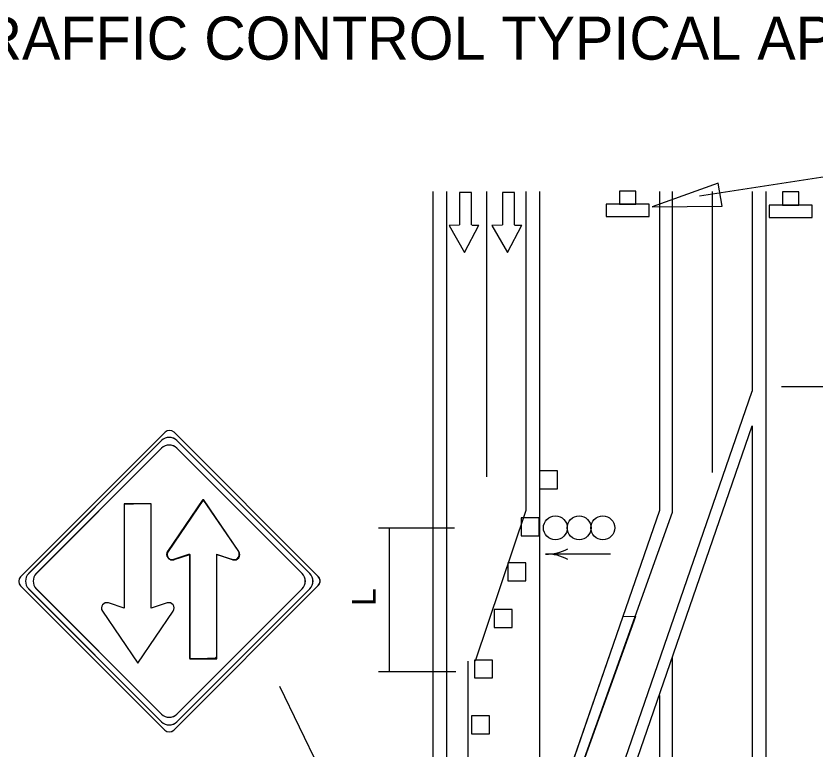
# Model space of a CAD drawing. Extents: x 1531.42 to 1538.58, y 1529.59 to 1539.57.
# Drawn here: x 1533.644 to 1535.649, y 1537.736 to 1539.575 of the extents above; entities that cross this region are included whole.
import ezdxf

# ---------------------------------------------------------------- set-up
doc = ezdxf.new("R2010")
doc.units = 0
for name, color, linetype in [('DETL-DIMS', 7, 'Continuous'), ('DETL-LINE', 7, 'Continuous'), ('DETL-NOTE', 7, 'Continuous'), ('DETL-TITL', 7, 'Continuous'), ('USER-BORD', 7, 'Continuous')]:
    doc.layers.add(name, color=color, linetype=linetype)

# ---------------------------------------------------------------- blocks, each defined once
blk = doc.blocks.new('PANEL0')
at = {"layer": 'USER-BORD'}
for centre in [(0.00309, -0.00012), (0.00928, -0.00012), (0.01546, -0.00012)]:
    blk.add_circle(centre, 0.00312, dxfattribs=at)
blk = doc.blocks.new('ZZZ')
at = {"layer": 'USER-BORD'}
blk.add_line((0.0185, 0), (0, 0), dxfattribs=at)
for centre, start, end in [((0.00034, 0.01233), 268.3695, 298.8797), ((0.00034, -0.01235), 61.1203, 91.6305)]:
    blk.add_arc(centre, 0.01234, start, end, dxfattribs=at)
blk = doc.blocks.new('R-BRD3')
at = {"layer": 'USER-BORD'}
for p, q in [((1.415, 2.996), (-1.412, 2.996)), ((-1.5, 2.909), (-1.5, 0.087)), ((-1.3, 2.95), (1.3, 2.95)), ((1.225, 2.875), (-1.225, 2.875)), ((1.502, 0.087), (1.502, 2.909)), ((-1.45, 0.2), (-1.45, 2.8)), ((1.45, 2.8), (1.45, 0.2)), ((-1.375, 2.725), (-1.375, 0.275)), ((1.375, 0.275), (1.375, 2.725)), ((-1.225, 0.125), (1.225, 0.125)), ((-1.412, 0), (1.415, 0)), ((1.3, 0.05), (-1.3, 0.05))]:
    blk.add_line(p, q, dxfattribs=at)
for centre, radius, start, end in [((-1.412, 2.909), 0.0875, 90, 180), ((1.415, 2.909), 0.0875, 0, 90), ((-1.3, 2.8), 0.15, 90, 180), ((-1.225, 2.725), 0.15, 90, 180), ((1.225, 2.725), 0.15, 0, 90), ((1.3, 2.8), 0.15, 0, 90), ((-1.225, 0.275), 0.15, 180, 270), ((1.225, 0.275), 0.15, 270, 0), ((-1.3, 0.2), 0.15, 180, 270), ((1.3, 0.2), 0.15, 270, 0), ((-1.412, 0.087), 0.0875, 180, 270), ((1.415, 0.087), 0.0875, 270, 0)]:
    blk.add_arc(centre, radius, start, end, dxfattribs=at)
blk = doc.blocks.new('W-BRD1')
at = {"layer": 'USER-BORD', "rotation": 45}
blk.add_blockref('R-BRD3', (1.0448, 1.0213), dxfattribs=at)

msp = doc.modelspace()

# ---------------------------------------------------------------- linework, layer by layer
at = {"layer": 'DETL-DIMS'}
for p, q in [((1536.0584, 1539.2298), (1535.359, 1539.1223)), ((1535.5651, 1538.6449), (1535.8056, 1538.6449)), ((1534.7442, 1538.29), (1534.554, 1538.29)), ((1534.5804, 1538.29), (1534.5804, 1537.9297)), ((1534.7477, 1537.9297), (1534.554, 1537.9297)), ((1534.5548, 1537.3801), (1534.3064, 1537.8927))]:
    msp.add_line(p, q, dxfattribs=at)
msp.add_lwpolyline([(1535.4162, 1539.0977), (1535.4066, 1539.1549), (1535.241, 1539.0959)], close=True, dxfattribs=at)
at = {"layer": 'DETL-LINE'}
for p, q in [((1534.6905, 1539.1347), (1534.6905, 1536.2958)), ((1534.724, 1539.1347), (1534.724, 1536.2958)), ((1534.7574, 1539.132), (1534.7574, 1539.051)), ((1534.7874, 1539.132), (1534.7574, 1539.132)), ((1534.7874, 1539.051), (1534.7874, 1539.132)), ((1534.8244, 1539.1347), (1534.8244, 1538.4186)), ((1534.8948, 1539.132), (1534.8649, 1539.132)), ((1534.8649, 1539.132), (1534.8649, 1539.051)), ((1534.8948, 1539.051), (1534.8948, 1539.132)), ((1534.9239, 1539.1347), (1534.9239, 1538.334)), ((1534.9574, 1539.1347), (1534.9574, 1537.4638)), ((1535.2586, 1539.1347), (1535.2586, 1538.334)), ((1535.2912, 1539.1347), (1535.2912, 1538.3287)), ((1535.3916, 1539.1347), (1535.3916, 1538.4291)), ((1535.492, 1539.1347), (1535.492, 1538.6335)), ((1535.5255, 1539.1347), (1535.5255, 1537.0031)), ((1534.731, 1539.0501), (1534.7574, 1539.051)), ((1534.731, 1539.0492), (1534.7698, 1538.9814)), ((1534.7698, 1538.9814), (1534.8058, 1539.0501)), ((1534.7882, 1539.0501), (1534.8058, 1539.0501)), ((1534.8384, 1539.0501), (1534.8649, 1539.051)), ((1534.8384, 1539.0492), (1534.8772, 1538.9814)), ((1534.8772, 1538.9814), (1534.9133, 1539.0501)), ((1534.8948, 1539.0501), (1534.9133, 1539.0501)), ((1534.9239, 1536.9925), (1535.492, 1538.6335)), ((1534.9574, 1536.9996), (1535.492, 1538.5463)), ((1535.492, 1538.5463), (1535.492, 1537.0031)), ((1534.018, 1538.5303), (1533.6552, 1538.1675)), ((1534.4024, 1538.1683), (1534.0405, 1538.5303)), ((1533.6756, 1538.176), (1534.0092, 1538.5096)), ((1534.0092, 1538.5096), (1533.6756, 1538.176)), ((1534.0477, 1538.5096), (1534.3813, 1538.176)), ((1534.3813, 1538.176), (1534.0477, 1538.5096)), ((1533.6948, 1538.1761), (1534.0092, 1538.4903)), ((1534.0476, 1538.4903), (1534.362, 1538.176)), ((1534.1132, 1538.362), (1534.0243, 1538.2316)), ((1534.1143, 1538.3613), (1534.0255, 1538.2309)), ((1534.1132, 1538.362), (1534.2019, 1538.2316)), ((1534.2031, 1538.2309), (1534.1143, 1538.3613)), ((1533.9384, 1538.3504), (1533.9154, 1538.3504)), ((1533.9154, 1538.3504), (1533.9154, 1538.1573)), ((1533.9834, 1538.3506), (1533.9166, 1538.3506)), ((1533.9166, 1538.3506), (1533.9384, 1538.3504)), ((1533.9834, 1538.1573), (1533.9834, 1538.3506)), ((1534.9239, 1538.334), (1534.7962, 1537.9561)), ((1535.2586, 1538.334), (1534.8358, 1537.1106)), ((1535.2912, 1538.3287), (1534.8543, 1537.1106)), ((1534.0792, 1538.2243), (1534.0395, 1538.2114)), ((1534.0407, 1538.2107), (1534.0804, 1538.2236)), ((1534.0791, 1538.2241), (1534.0791, 1538.1561)), ((1534.0803, 1538.2234), (1534.0803, 1538.1553)), ((1534.1471, 1538.2243), (1534.1868, 1538.2114)), ((1534.1472, 1538.2241), (1534.1472, 1538.1561)), ((1534.1482, 1538.2236), (1534.1879, 1538.2107)), ((1534.1483, 1538.1553), (1534.1483, 1538.2234)), ((1533.9154, 1538.1573), (1533.9154, 1538.0893)), ((1533.9834, 1538.0893), (1533.9834, 1538.1573)), ((1534.0791, 1538.1561), (1534.0791, 1537.9628)), ((1534.1472, 1538.1561), (1534.1472, 1537.963)), ((1533.6552, 1538.1451), (1534.0172, 1537.7831)), ((1534.0092, 1537.8039), (1533.6756, 1538.1375)), ((1533.6756, 1538.1375), (1534.0092, 1537.8039)), ((1534.0092, 1537.8232), (1533.6948, 1538.1375)), ((1534.0396, 1537.7831), (1534.4024, 1538.1459)), ((1534.3813, 1538.1375), (1534.0477, 1537.8039)), ((1534.362, 1538.1375), (1534.0477, 1537.8232)), ((1534.0477, 1537.8039), (1534.3813, 1538.1375)), ((1534.0803, 1538.1553), (1534.0803, 1537.9621)), ((1534.1483, 1537.9623), (1534.1483, 1538.1553)), ((1533.9155, 1538.0891), (1533.8758, 1538.102)), ((1534.023, 1538.102), (1533.9834, 1538.0891)), ((1533.8606, 1538.0818), (1533.9494, 1537.9514)), ((1533.9494, 1537.9514), (1534.0382, 1538.0818)), ((1534.0791, 1537.9628), (1534.146, 1537.9628)), ((1534.0803, 1537.9621), (1534.1471, 1537.9621)), ((1534.1472, 1537.963), (1534.1241, 1537.963)), ((1534.1253, 1537.9623), (1534.1483, 1537.9623)), ((1534.1471, 1537.9621), (1534.1253, 1537.9623)), ((1534.1432, 1537.9628), (1534.1471, 1537.9669)), ((1534.7777, 1537.9561), (1534.7777, 1536.6279)), ((1535.2912, 1537.9667), (1535.2912, 1537.1335)), ((1533.9492, 1537.9517), (1533.9507, 1537.9532)), ((1535.2586, 1537.8698), (1535.2586, 1537.1335))]:
    msp.add_line(p, q, dxfattribs=at)
for points in [[(1535.1587, 1539.1025), (1535.2, 1539.1025), (1535.2, 1539.1353), (1535.1587, 1539.1353)], [(1535.5676, 1539.1003), (1535.6089, 1539.1003), (1535.6089, 1539.1331), (1535.5676, 1539.1331)], [(1535.1251, 1539.1025), (1535.1251, 1539.0716), (1535.2333, 1539.0716), (1535.2333, 1539.1025)], [(1535.534, 1539.1003), (1535.534, 1539.0695), (1535.6422, 1539.0695), (1535.6422, 1539.1003)], [(1534.958, 1538.3886), (1535.0028, 1538.3886), (1535.0028, 1538.4334), (1534.958, 1538.4334)], [(1534.9122, 1538.2706), (1534.957, 1538.2706), (1534.957, 1538.3154), (1534.9122, 1538.3154)], [(1534.8787, 1538.1579), (1534.9235, 1538.1579), (1534.9235, 1538.2027), (1534.8787, 1538.2027)], [(1534.8444, 1538.0407), (1534.8892, 1538.0407), (1534.8892, 1538.0855), (1534.8444, 1538.0855)], [(1535.1679, 1538.0689), (1535.1987, 1538.068), (1534.8552, 1537.1115), (1534.8437, 1537.1317)], [(1534.795, 1537.9139), (1534.8398, 1537.9139), (1534.8398, 1537.9587), (1534.795, 1537.9587)], [(1534.7871, 1537.7738), (1534.8319, 1537.7738), (1534.8319, 1537.8186), (1534.7871, 1537.8186)]]:
    msp.add_lwpolyline(points, close=True, dxfattribs=at)
for points in [[(1534.8244, 1538.9847), (1534.8244, 1538.8847)], [(1535.3916, 1538.9847), (1535.3916, 1538.8847)], [(1534.8244, 1538.5847), (1534.8244, 1538.4847)], [(1535.3916, 1538.5847), (1535.3916, 1538.4847)]]:
    msp.add_lwpolyline(points, dxfattribs=at)
for centre, radius, start, end in [((1534.0285, 1538.4903), 0.0272, 45, 135), ((1534.0285, 1538.4903), 0.0272, 45, 135), ((1534.0292, 1538.5191), 0.0159, 45, 135), ((1534.0284, 1538.4711), 0.0272, 45, 135), ((1534.0354, 1538.2241), 0.0134, 145.7397, 288), ((1534.0365, 1538.2234), 0.0134, 145.7397, 288), ((1534.1909, 1538.2241), 0.0134, 252, 34.2603), ((1534.1921, 1538.2234), 0.0134, 252, 34.2603), ((1533.6665, 1538.1563), 0.0159, 135, 225), ((1533.6949, 1538.1567), 0.0272, 135, 225), ((1533.6949, 1538.1567), 0.0272, 135, 225), ((1533.7141, 1538.1568), 0.0272, 135, 225), ((1534.3428, 1538.1567), 0.0272, 315, 45), ((1534.362, 1538.1567), 0.0272, 315, 45), ((1534.362, 1538.1567), 0.0272, 315, 45), ((1534.3912, 1538.1571), 0.0159, 315, 45), ((1533.8717, 1538.0893), 0.0134, 72, 214.2603), ((1534.0272, 1538.0893), 0.0134, 325.7397, 108), ((1534.0284, 1537.8424), 0.0272, 225, 315), ((1534.0285, 1537.8232), 0.0272, 225, 315), ((1534.0285, 1537.8232), 0.0272, 225, 315), ((1534.0284, 1537.7943), 0.0159, 225, 315)]:
    msp.add_arc(centre, radius, start, end, dxfattribs=at)

# ---------------------------------------------------------------- block references
for name, p, xscale, yscale in [('W-BRD1', (1534.0314, 1537.779), 0.1814448, 0.18144479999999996), ('PANEL0', (1534.9679, 1538.2917), 9.618403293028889, 9.618403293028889), ('ZZZ', (1534.9732, 1538.2248), 8.807999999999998, 8.807999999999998)]:
    msp.add_blockref(name, p, dxfattribs=dict(at, xscale=xscale, yscale=yscale))

# ---------------------------------------------------------------- texts
at = {"layer": 'DETL-NOTE'}
msp.add_text('L', height=0.06, rotation=90, dxfattribs=at).set_placement((1534.5469, 1538.0947))
at = {"layer": 'DETL-TITL'}
msp.add_text('TEMPORARY TRAFFIC CONTROL TYPICAL APPLICATION', height=0.108, dxfattribs=at).set_placement((1532.5115, 1539.465))

doc.saveas('drawing.dxf')
